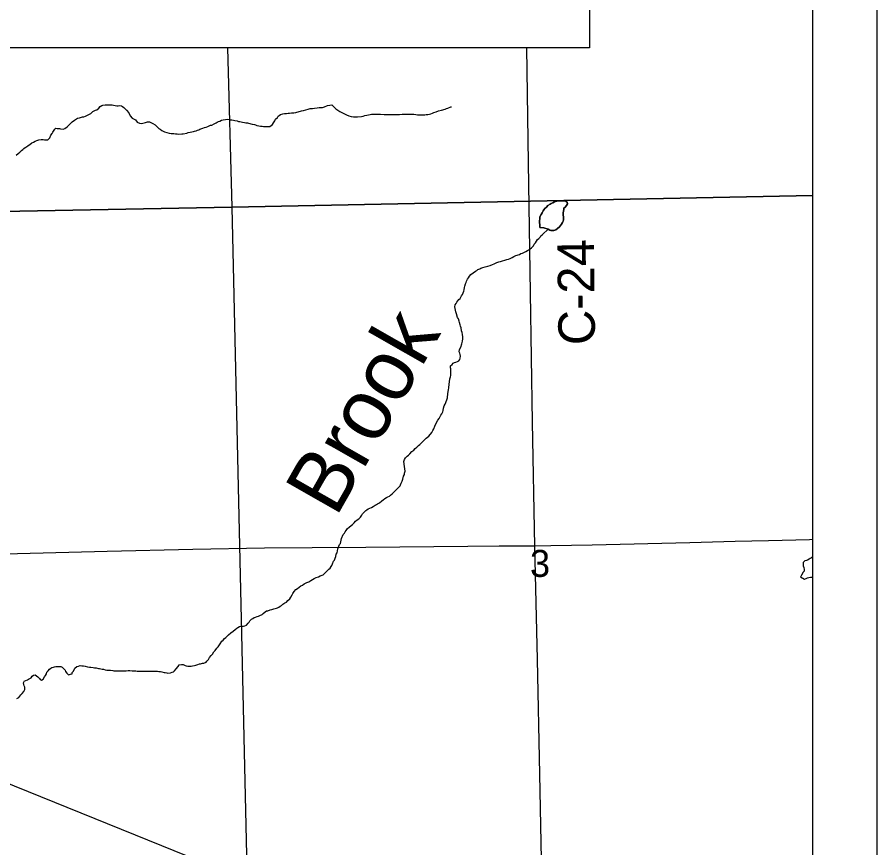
# Model space of a CAD drawing. Extents: x 10.6 to 44.6, y -2.6 to 23.4.
# Drawn here: x 18.767 to 20.103, y 17.784 to 19.074 of the extents above; entities that cross this region are included whole.
import ezdxf

# ---------------------------------------------------------------- set-up
doc = ezdxf.new("R2010")
doc.units = 0
for name, color, linetype in [('GM_X_County', 7, 'Continuous'), ('GM_X_County_Road', 7, 'Continuous'), ('GM_X_County_Road_Text', 7, 'Continuous'), ('GM_X_Minor_Lake', 7, 'Continuous'), ('GM_X_Minor_River', 7, 'Continuous'), ('GM_X_Minor_River_Text', 7, 'Continuous'), ('GM_X_Section', 7, 'Continuous'), ('GM_X_Section_Text', 7, 'Continuous'), ('GM_X_Township', 7, 'Continuous'), ('GM_X_Township_Road', 7, 'Continuous'), ('GM_X_US_Route', 7, 'Continuous'), ('SH_Border', 7, 'Continuous'), ('SH_Data', 7, 'Continuous')]:
    doc.layers.add(name, color=color, linetype=linetype)

msp = doc.modelspace()

# ---------------------------------------------------------------- linework, layer by layer
at = {"layer": 'GM_X_County'}
msp.add_lwpolyline([(20.0033, 15.5302), (20.0033, 22.3267), (13.2033, 22.3267), (13.2033, 15.5267), (19.8413, 15.5267)], dxfattribs=at)
at = {"layer": 'GM_X_County_Road'}
msp.add_lwpolyline([(19.5848, 17.5467), (19.5826, 17.712), (19.5792, 17.8983), (19.5753, 18.0763), (19.5711, 18.2524), (19.5677, 18.4449), (19.5648, 18.6461), (19.5616, 18.8476), (19.5588, 19.0263)], dxfattribs=at)
at = {"layer": 'GM_X_Minor_Lake'}
for points in [[(19.6199, 18.7875), (19.6172, 18.7886), (19.615, 18.7889), (19.6123, 18.7889), (19.6104, 18.7889), (19.6081, 18.7889), (19.6055, 18.7885), (19.6036, 18.7877), (19.6017, 18.7873), (19.5994, 18.7858), (19.5968, 18.7846), (19.5949, 18.7835), (19.5915, 18.7815), (19.5892, 18.7792), (19.587, 18.777), (19.5855, 18.775), (19.5843, 18.7731), (19.5825, 18.7701), (19.5814, 18.7674), (19.5791, 18.764), (19.5791, 18.7606), (19.5788, 18.7579), (19.5788, 18.7552), (19.5792, 18.7514), (19.5792, 18.7476), (19.5855, 18.7466)], [(19.5855, 18.7466), (19.5792, 18.7476), (19.5792, 18.7514), (19.5788, 18.7552), (19.5788, 18.7579), (19.5791, 18.7606), (19.5791, 18.764), (19.5814, 18.7674), (19.5825, 18.7701), (19.5843, 18.7731), (19.5855, 18.775), (19.587, 18.777), (19.5892, 18.7792), (19.5915, 18.7815), (19.5949, 18.7835), (19.5968, 18.7846), (19.5994, 18.7858), (19.6017, 18.7873), (19.6036, 18.7877), (19.6055, 18.7885), (19.6081, 18.7889), (19.6104, 18.7889), (19.6123, 18.7889), (19.615, 18.7889), (19.6172, 18.7886), (19.6199, 18.7875), (19.6218, 18.7867), (19.6222, 18.784), (19.6207, 18.7818), (19.6185, 18.7787), (19.6166, 18.7775), (19.6162, 18.7753), (19.6158, 18.7726), (19.6155, 18.7699), (19.6155, 18.768), (19.6155, 18.7661), (19.6159, 18.7642), (19.6159, 18.7623), (19.6159, 18.7593), (19.6152, 18.757), (19.6141, 18.7551), (19.6126, 18.7524), (19.6096, 18.7482), (19.6066, 18.7456), (19.6039, 18.744), (19.6009, 18.7429), (19.599, 18.7428), (19.5963, 18.7428), (19.5944, 18.7432), (19.5918, 18.7447), (19.5855, 18.7466)], [(19.5855, 18.7466), (19.5918, 18.7447), (19.5944, 18.7432), (19.5963, 18.7428), (19.599, 18.7428), (19.6009, 18.7429), (19.6039, 18.744), (19.6066, 18.7456), (19.6096, 18.7482), (19.6126, 18.7524), (19.6141, 18.7551), (19.6152, 18.757), (19.6159, 18.7593), (19.6159, 18.7623), (19.6159, 18.7642), (19.6155, 18.7661), (19.6155, 18.768), (19.6155, 18.7699), (19.6158, 18.7726), (19.6162, 18.7753), (19.6166, 18.7775), (19.6185, 18.7787), (19.6207, 18.7818), (19.6222, 18.784), (19.6218, 18.7867), (19.6199, 18.7875)], [(20.0033, 18.2355), (20.0032, 18.2355), (20.0013, 18.2343), (19.9994, 18.2332), (19.9976, 18.232), (19.9953, 18.2308), (19.9934, 18.2301), (19.9907, 18.2297), (19.9885, 18.227), (19.9885, 18.224), (19.9885, 18.2217), (19.9893, 18.2194), (19.9901, 18.216), (19.9897, 18.2137), (19.9886, 18.2118), (19.986, 18.2072), (19.9845, 18.2053), (19.9842, 18.2046)], [(19.9842, 18.2046), (19.9902, 18.2012), (19.9928, 18.2023), (19.9951, 18.2031), (19.997, 18.2039), (19.9997, 18.2043), (20.0023, 18.2043), (20.0033, 18.2043)]]:
    msp.add_lwpolyline(points, dxfattribs=at)
at = {"layer": 'GM_X_Minor_River'}
for points in [[(18.7654, 18.8599), (18.7685, 18.8625), (18.7707, 18.8645), (18.7737, 18.8671), (18.7756, 18.8683), (18.7771, 18.8702), (18.7794, 18.8717), (18.7813, 18.8729), (18.7839, 18.8748), (18.7866, 18.8764), (18.7896, 18.8787), (18.7919, 18.8798), (18.7945, 18.8814), (18.7971, 18.8825), (18.8006, 18.8837), (18.804, 18.8841), (18.807, 18.8841), (18.8093, 18.8837), (18.8116, 18.8834), (18.8142, 18.8838), (18.8176, 18.8868), (18.8191, 18.8907), (18.821, 18.8933), (18.8221, 18.8956), (18.8251, 18.9002), (18.827, 18.9017), (18.8289, 18.901), (18.8323, 18.901), (18.8342, 18.9006), (18.838, 18.9003), (18.841, 18.9011), (18.8444, 18.9038), (18.8463, 18.9057), (18.8493, 18.9084), (18.852, 18.9114), (18.8557, 18.9141), (18.8606, 18.9172), (18.8637, 18.9176), (18.8682, 18.9191), (18.8705, 18.9195), (18.8728, 18.9203), (18.8781, 18.923), (18.8811, 18.9245), (18.8845, 18.9276), (18.8883, 18.9295), (18.8905, 18.9303), (18.8935, 18.933), (18.8958, 18.9353), (18.8981, 18.9368), (18.9, 18.9376), (18.9034, 18.938), (18.9068, 18.938), (18.9091, 18.938), (18.9117, 18.9381), (18.9144, 18.9377), (18.9167, 18.9373), (18.9189, 18.937), (18.9216, 18.9366), (18.9239, 18.9366), (18.9262, 18.9367), (18.9288, 18.9363), (18.9307, 18.9355), (18.9326, 18.934), (18.9353, 18.9314), (18.9368, 18.9295), (18.9403, 18.9257), (18.9426, 18.9208), (18.9457, 18.9174), (18.9487, 18.9155), (18.9506, 18.9148), (18.9533, 18.911), (18.9571, 18.9095), (18.9601, 18.9088), (18.962, 18.9096), (18.9643, 18.91), (18.9662, 18.9107), (18.9692, 18.9115), (18.9726, 18.9115)], [(18.9726, 18.9115), (18.9753, 18.91), (18.9776, 18.9089), (18.981, 18.9067), (18.9837, 18.9044), (18.9871, 18.9014), (18.9891, 18.8999), (18.9917, 18.898), (18.9959, 18.8961), (18.9993, 18.895), (19.0028, 18.8939), (19.0062, 18.8935), (19.0081, 18.8932), (19.0104, 18.8932), (19.013, 18.8928), (19.0153, 18.8928), (19.018, 18.8925), (19.0225, 18.8929), (19.0248, 18.8929), (19.0305, 18.8941), (19.0327, 18.8949), (19.0354, 18.8953), (19.038, 18.8961), (19.0407, 18.8965), (19.0426, 18.8968), (19.0449, 18.8976), (19.0468, 18.8984), (19.049, 18.8992), (19.0509, 18.8999), (19.0551, 18.9015), (19.0577, 18.9027), (19.0604, 18.9034), (19.063, 18.9042), (19.0649, 18.9054), (19.0672, 18.9061), (19.0691, 18.9065), (19.0729, 18.9085), (19.0759, 18.91), (19.0778, 18.9112), (19.0797, 18.9119), (19.0819, 18.9127), (19.0842, 18.9139), (19.0869, 18.9146), (19.0903, 18.9154), (19.0929, 18.9155), (19.0963, 18.9151), (19.0982, 18.9147), (19.1005, 18.9144), (19.1028, 18.914), (19.1051, 18.9136), (19.1085, 18.9129), (19.1108, 18.9122), (19.1127, 18.9118), (19.115, 18.9114), (19.1172, 18.9111), (19.1199, 18.9107), (19.1222, 18.91), (19.1245, 18.91), (19.1264, 18.9096), (19.1321, 18.9081), (19.1355, 18.9074), (19.1374, 18.9067), (19.1393, 18.9059), (19.1423, 18.9052), (19.145, 18.9048), (19.1473, 18.9048), (19.1496, 18.9045), (19.1515, 18.9041), (19.1541, 18.9041), (19.1568, 18.9041), (19.1594, 18.9042), (19.1617, 18.9057), (19.1636, 18.9072), (19.1651, 18.9099), (19.1673, 18.913), (19.1685, 18.9156), (19.1711, 18.9183), (19.1722, 18.9202), (19.1741, 18.9214), (19.176, 18.9229), (19.1798, 18.9241), (19.1824, 18.9245), (19.1851, 18.9245), (19.1877, 18.9249), (19.19, 18.9249), (19.193, 18.9253), (19.1968, 18.9257), (19.1999, 18.9261), (19.2086, 18.9285), (19.212, 18.9292), (19.2154, 18.9304), (19.2192, 18.9312), (19.2222, 18.932), (19.2256, 18.9324), (19.229, 18.9328), (19.2332, 18.9332), (19.2359, 18.9336), (19.2385, 18.934), (19.2412, 18.934), (19.2446, 18.9348), (19.2491, 18.9367)], [(19.2491, 18.9367), (19.2529, 18.9375), (19.256, 18.9379), (19.2594, 18.9345), (19.2621, 18.9319), (19.2651, 18.9296), (19.2682, 18.9274), (19.2724, 18.9255), (19.2754, 18.924), (19.2788, 18.9225), (19.2823, 18.921), (19.2861, 18.9199), (19.2895, 18.9192), (19.2929, 18.9192), (19.2956, 18.9192), (19.302, 18.9196), (19.3047, 18.9204), (19.3073, 18.9212), (19.3103, 18.922), (19.313, 18.9224), (19.3153, 18.9228), (19.3175, 18.9232), (19.3202, 18.9236), (19.3221, 18.9236), (19.3244, 18.9236), (19.3278, 18.9233), (19.3316, 18.9233), (19.3369, 18.9229), (19.3411, 18.923), (19.3453, 18.923), (19.3487, 18.923), (19.3528, 18.9231), (19.3566, 18.9231), (19.3608, 18.9231), (19.365, 18.9235), (19.3692, 18.9236), (19.373, 18.9236), (19.3764, 18.9236), (19.3805, 18.9233), (19.3832, 18.9233), (19.3862, 18.9229), (19.3889, 18.9226), (19.3916, 18.9226), (19.3938, 18.9226), (19.3965, 18.9226), (19.3984, 18.9223), (19.4003, 18.9223), (19.4026, 18.9227), (19.4052, 18.9231), (19.4075, 18.9235), (19.4098, 18.9242), (19.4124, 18.925), (19.4143, 18.9258), (19.4177, 18.9273), (19.4215, 18.9285), (19.4264, 18.9297), (19.4317, 18.9312), (19.434, 18.932), (19.4359, 18.9328), (19.4408, 18.9347), (19.4416, 18.9347)], [(19.5918, 18.7447), (19.5918, 18.7447), (19.583, 18.7364)], [(19.4875, 18.6843), (19.4905, 18.6854), (19.4939, 18.6862), (19.4981, 18.6874), (19.5019, 18.6885), (19.5053, 18.6897), (19.5079, 18.6909), (19.5102, 18.692), (19.5125, 18.6928), (19.5155, 18.694), (19.5181, 18.6947), (19.5212, 18.6955), (19.5246, 18.6967), (19.5276, 18.6975), (19.5303, 18.6983), (19.5329, 18.6994), (19.5359, 18.701), (19.5386, 18.7025), (19.5416, 18.7037), (19.5473, 18.7056), (19.5495, 18.7068), (19.5522, 18.7075), (19.5541, 18.7083), (19.5575, 18.7102), (19.5598, 18.7114), (19.562, 18.7129), (19.5639, 18.7141), (19.5662, 18.716), (19.5692, 18.7191), (19.5703, 18.7214), (19.5722, 18.7233), (19.5741, 18.7259), (19.5752, 18.7286), (19.5775, 18.7301), (19.5797, 18.7324), (19.5808, 18.7343), (19.583, 18.7364)], [(19.3852, 18.4038), (19.3879, 18.4061), (19.3905, 18.4088), (19.3924, 18.4104), (19.3943, 18.4119), (19.3962, 18.4138), (19.398, 18.4157), (19.4003, 18.418), (19.4022, 18.4199), (19.4044, 18.4215), (19.4063, 18.4234), (19.4112, 18.4287), (19.4127, 18.4322), (19.4142, 18.4348), (19.4157, 18.439), (19.4179, 18.4432), (19.4206, 18.4482), (19.4224, 18.4509), (19.4239, 18.4528), (19.4254, 18.4558), (19.4266, 18.4577), (19.4281, 18.4608), (19.4288, 18.4631), (19.4295, 18.4665), (19.4306, 18.4703), (19.4321, 18.473), (19.4329, 18.4753), (19.4336, 18.4772), (19.4344, 18.4798), (19.4355, 18.4829), (19.4362, 18.4897), (19.4369, 18.495), (19.4376, 18.4985), (19.4384, 18.5042), (19.4387, 18.5076), (19.4391, 18.5122), (19.4402, 18.5156), (19.4405, 18.5175), (19.4409, 18.5239), (19.4409, 18.5258), (19.4408, 18.5277), (19.4404, 18.5296), (19.4404, 18.5323), (19.4427, 18.5346), (19.4442, 18.5365), (19.4465, 18.5377), (19.4484, 18.5381), (19.451, 18.5392), (19.4533, 18.54), (19.4548, 18.5423), (19.4555, 18.5442), (19.4559, 18.5476), (19.4555, 18.5499), (19.4547, 18.5522), (19.4535, 18.5544), (19.4543, 18.5579), (19.4561, 18.5617), (19.458, 18.5666), (19.4587, 18.5708), (19.4595, 18.5746), (19.4594, 18.5773), (19.4587, 18.5811), (19.4583, 18.5841), (19.4575, 18.5868), (19.4567, 18.5913), (19.4559, 18.594), (19.4551, 18.5963), (19.4543, 18.6), (19.4536, 18.6019), (19.4528, 18.6054), (19.4512, 18.6076), (19.4493, 18.6133), (19.4485, 18.6163), (19.4473, 18.6213), (19.4469, 18.6239), (19.4473, 18.6274), (19.4488, 18.6293), (19.4503, 18.6316), (19.4518, 18.6335), (19.4533, 18.6354), (19.4552, 18.6373), (19.4563, 18.6392), (19.4574, 18.6411), (19.4589, 18.6434), (19.4612, 18.6487), (19.4615, 18.6506), (19.4619, 18.6541), (19.4623, 18.656), (19.4634, 18.6598), (19.4645, 18.6621), (19.4652, 18.664), (19.4667, 18.667), (19.4682, 18.6693), (19.4697, 18.6716), (19.472, 18.6743), (19.4754, 18.677), (19.4792, 18.6796), (19.4811, 18.6808), (19.4829, 18.682), (19.4856, 18.6831), (19.4875, 18.6843)], [(19.1753, 18.1591), (19.1776, 18.1603), (19.1798, 18.1622), (19.1829, 18.1641), (19.1851, 18.1653), (19.1874, 18.1679), (19.1904, 18.1706), (19.1923, 18.1733), (19.1941, 18.1767), (19.1953, 18.1786), (19.1975, 18.1821), (19.1998, 18.1848), (19.2024, 18.1867), (19.2051, 18.1886), (19.2077, 18.1905), (19.21, 18.192), (19.213, 18.194), (19.2149, 18.1951), (19.2172, 18.1959), (19.2198, 18.1971), (19.2232, 18.199), (19.2258, 18.2005), (19.2285, 18.2021), (19.2315, 18.2036), (19.2349, 18.2048), (19.2379, 18.2063), (19.2421, 18.2079), (19.2444, 18.2098), (19.2463, 18.2117), (19.2489, 18.2144), (19.2512, 18.2167), (19.2534, 18.2182), (19.2549, 18.2205), (19.2557, 18.2224), (19.2568, 18.2247), (19.2586, 18.2289), (19.2598, 18.2308), (19.2609, 18.2338), (19.262, 18.2365), (19.2627, 18.2399), (19.2642, 18.2422), (19.265, 18.2483), (19.2679, 18.2548), (19.2691, 18.2567), (19.2709, 18.2643), (19.2735, 18.2704), (19.2754, 18.2723), (19.2765, 18.2746), (19.278, 18.2769), (19.2803, 18.2796), (19.2825, 18.2819), (19.2856, 18.2842), (19.2878, 18.2861), (19.2905, 18.2888), (19.2927, 18.2911), (19.2954, 18.293), (19.2976, 18.2949), (19.3006, 18.2976), (19.3025, 18.3006), (19.3036, 18.3025), (19.3055, 18.3048), (19.3085, 18.3075), (19.3104, 18.3087), (19.3123, 18.3102), (19.315, 18.3114), (19.3172, 18.3125), (19.3199, 18.3141), (19.3233, 18.316), (19.3252, 18.3171), (19.327, 18.3183), (19.3301, 18.3198), (19.3335, 18.3225), (19.3357, 18.3244), (19.338, 18.3264), (19.3406, 18.3279), (19.3429, 18.3291), (19.3452, 18.3302), (19.3471, 18.3317), (19.3497, 18.3337), (19.3516, 18.3356), (19.3538, 18.3379), (19.3565, 18.3406), (19.3618, 18.3459), (19.3625, 18.3478), (19.3636, 18.3501), (19.3651, 18.3535), (19.3659, 18.3562), (19.367, 18.3611), (19.3685, 18.3638), (19.3688, 18.3657), (19.3696, 18.3688), (19.3687, 18.376), (19.3679, 18.384), (19.3687, 18.387), (19.3705, 18.3897), (19.3728, 18.392), (19.3747, 18.3939), (19.3769, 18.3958), (19.3803, 18.3992), (19.383, 18.4015), (19.3852, 18.4038)], [(18.9305, 18.0589), (18.9339, 18.0589), (18.9362, 18.0589), (18.9392, 18.059), (18.9419, 18.059), (18.9457, 18.0586), (18.9484, 18.0587), (18.9514, 18.0587), (18.9533, 18.0583), (18.9556, 18.0583), (18.9582, 18.058), (18.9613, 18.058), (18.9635, 18.058), (18.9658, 18.058), (18.9677, 18.058), (18.9711, 18.0581), (18.973, 18.0581), (18.9749, 18.0581), (18.9772, 18.0581), (18.9795, 18.0581), (18.9818, 18.0581), (18.9848, 18.0582), (18.9867, 18.0578), (18.9893, 18.0578), (18.9916, 18.0571), (18.995, 18.0563), (18.9969, 18.056), (18.9992, 18.0556), (19.0011, 18.0552), (19.0049, 18.0556), (19.0076, 18.0568), (19.0095, 18.0572), (19.0114, 18.0587), (19.014, 18.0618), (19.017, 18.0656), (19.0185, 18.0679), (19.0219, 18.0687), (19.0246, 18.0687), (19.0276, 18.0672), (19.0295, 18.0665), (19.0318, 18.0657), (19.0337, 18.0657), (19.0371, 18.0661), (19.039, 18.0662), (19.0424, 18.0669), (19.0443, 18.0677), (19.0473, 18.0685), (19.05, 18.0693), (19.0519, 18.0697), (19.0549, 18.0705), (19.0568, 18.0708), (19.0606, 18.072), (19.0617, 18.0739), (19.064, 18.0762), (19.0658, 18.0793), (19.0681, 18.0823), (19.0704, 18.0846), (19.0726, 18.0884), (19.0745, 18.0904), (19.0771, 18.0938), (19.079, 18.0957), (19.0824, 18.1007), (19.0846, 18.1045), (19.0869, 18.1064), (19.0891, 18.1091), (19.091, 18.1106), (19.0929, 18.1125), (19.0952, 18.1144), (19.0986, 18.1175), (19.1024, 18.1202), (19.1057, 18.1229), (19.108, 18.1248), (19.1099, 18.126), (19.1125, 18.1275), (19.1156, 18.1279), (19.1186, 18.1283), (19.1205, 18.1287), (19.1232, 18.1295), (19.1258, 18.1325), (19.1273, 18.1344), (19.1284, 18.1364), (19.1307, 18.139), (19.1329, 18.1402), (19.1352, 18.1413), (19.1371, 18.1421), (19.1398, 18.1429), (19.142, 18.1437), (19.1439, 18.1444), (19.1473, 18.1464), (19.1492, 18.1475), (19.1522, 18.1502), (19.1545, 18.1517), (19.1564, 18.1521), (19.1602, 18.1533), (19.1624, 18.1537), (19.1658, 18.1549), (19.1677, 18.1553), (19.1696, 18.156), (19.1715, 18.1564), (19.1734, 18.1576), (19.1753, 18.1591)], [(18.7661, 18.0155), (18.7692, 18.0171), (18.7725, 18.0216), (18.7744, 18.0232), (18.7771, 18.0266), (18.7785, 18.0297), (18.7785, 18.0331), (18.7774, 18.0354), (18.777, 18.0373), (18.7766, 18.0399), (18.7781, 18.043), (18.78, 18.0437), (18.7826, 18.0449), (18.7845, 18.0457), (18.7864, 18.0465), (18.7887, 18.048), (18.7902, 18.0503), (18.792, 18.0518), (18.7947, 18.0526), (18.7966, 18.0511), (18.7989, 18.0492), (18.8012, 18.0469), (18.8023, 18.045), (18.8046, 18.0443), (18.8073, 18.0458), (18.8091, 18.0493), (18.8106, 18.0516), (18.8121, 18.0539), (18.8129, 18.0565), (18.8151, 18.0588), (18.817, 18.0615), (18.8189, 18.063), (18.8208, 18.0638), (18.8231, 18.0642), (18.825, 18.065), (18.8269, 18.0654), (18.8318, 18.0654), (18.8348, 18.0654), (18.8367, 18.0643), (18.839, 18.0624), (18.8413, 18.0598), (18.8421, 18.0575), (18.844, 18.0549), (18.8467, 18.0526), (18.8497, 18.0534), (18.852, 18.0538), (18.852, 18.0561), (18.8542, 18.0583), (18.8565, 18.0629), (18.8595, 18.0656), (18.8621, 18.066), (18.8644, 18.0668), (18.8675, 18.0664), (18.8697, 18.0664), (18.8724, 18.0657), (18.8758, 18.065), (18.8792, 18.0646), (18.8811, 18.0646), (18.8849, 18.0639), (18.8868, 18.0635), (18.8895, 18.0632), (18.8929, 18.0624), (18.8948, 18.0621), (18.8967, 18.0617), (18.899, 18.0613), (18.9009, 18.061), (18.9036, 18.0602), (18.9062, 18.0599), (18.9093, 18.0599), (18.9119, 18.0595), (18.9153, 18.0592), (18.9172, 18.0588), (18.9191, 18.0588), (18.9214, 18.0588), (18.9241, 18.0589), (18.9275, 18.0589), (18.9305, 18.0589)]]:
    msp.add_lwpolyline(points, dxfattribs=at)
at = {"layer": 'GM_X_Section'}
for p, q in [((20.0033, 18.797), (20.0033, 19.8622)), ((20.0033, 17.685), (20.0033, 18.797))]:
    msp.add_line(p, q, dxfattribs=at)
for points in [[(19.0934, 19.0263), (19.1006, 18.7791), (18.1656, 18.7612), (18.1646, 18.8031), (18.1592, 19.0263)], [(19.0934, 19.0263), (19.1006, 18.7791), (20.0033, 18.797)], [(20.0033, 18.797), (19.1006, 18.7791), (19.125, 17.681), (20.0033, 17.685)]]:
    msp.add_lwpolyline(points, dxfattribs=at)
msp.add_lwpolyline([(18.1656, 18.7612), (19.1006, 18.7791), (19.125, 17.681), (18.1848, 17.6775)], close=True, dxfattribs=at)
at = {"layer": 'GM_X_Township'}
msp.add_line((20.0033, 15.5302), (20.0033, 20.9573), dxfattribs=at)
at = {"layer": 'GM_X_Township_Road'}
for points in [[(19.5711, 18.2524), (19.5157, 18.2521), (19.4672, 18.2519), (19.3087, 18.2504), (19.2254, 18.2496), (19.1509, 18.2493), (19.0398, 18.2473), (18.9064, 18.2438), (18.7671, 18.2405), (18.7032, 18.2388), (18.6092, 18.236), (18.5638, 18.2353)], [(20.0033, 18.2625), (19.998, 18.2624), (19.9345, 18.2607), (19.8825, 18.2594), (19.8123, 18.2576), (19.6606, 18.2541), (19.596, 18.2526), (19.5711, 18.2524)]]:
    msp.add_lwpolyline(points, dxfattribs=at)
at = {"layer": 'GM_X_US_Route'}
msp.add_lwpolyline([(18.6315, 17.9333), (18.762, 17.8801), (19.0322, 17.771), (19.2878, 17.6674), (19.4378, 17.6063), (19.483, 17.588)], dxfattribs=at)
at = {"layer": 'SH_Border'}
msp.add_lwpolyline([(17.8388, 19.5913), (19.6562, 19.5913), (19.6562, 19.0263), (17.8388, 19.0263)], close=True, dxfattribs=at)
at = {"layer": 'SH_Data'}
msp.add_line((20.1028, 22.4265), (20.1028, 15.4265), dxfattribs=at)

# ---------------------------------------------------------------- texts
at = {"layer": 'GM_X_County_Road_Text'}
msp.add_text('C-24', height=0.05682, rotation=90.6858, dxfattribs=at).set_placement((19.665, 18.5649))
at = {"layer": 'GM_X_Minor_River_Text'}
msp.add_text('Brook', height=0.09476, rotation=60.3298, dxfattribs=at).set_placement((19.2622, 18.2957))
at = {"layer": 'GM_X_Section_Text'}
msp.add_text('3', height=0.0419, rotation=0, dxfattribs=at).set_placement((19.5638, 18.2046))

doc.saveas('drawing.dxf')
